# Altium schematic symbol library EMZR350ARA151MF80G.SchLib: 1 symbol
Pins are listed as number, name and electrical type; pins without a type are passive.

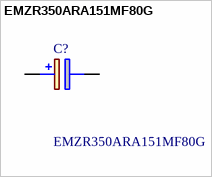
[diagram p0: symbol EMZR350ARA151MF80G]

## EMZR350ARA151MF80G
designator C?
Aluminum Electrolytic Capacitors - SMD 150uF 35V 20%; Manufacturer_Name: Chemi-Con; Geometry.Height: 8mm
footprint CAPAE660X800N
pins: 1 +, 2 -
